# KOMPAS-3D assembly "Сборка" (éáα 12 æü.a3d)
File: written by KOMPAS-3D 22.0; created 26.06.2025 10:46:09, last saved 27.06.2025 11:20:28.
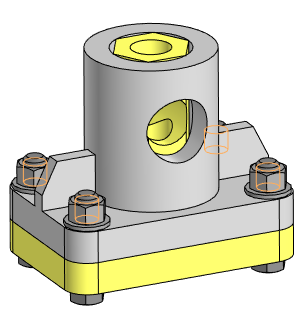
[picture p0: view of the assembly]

Document properties: Автор: Helen; Полное имя файла: C:\Для ноута\Инженерная графика\ППЭ 2025-2026\Варианты 1-38\Вариант 12 СБ\Вар 12 СБ\Вар 12 СБ.a3d

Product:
- Component [detail]: Сборка  | qty 4  | Масса: 0.008612; source file: ..\..\Вариант 8 СБ\Вар 8 СБ\Шайба 14.m3d
- Component [detail]: Сборка  | qty 4  | Масса: 0.02533; source file: ..\..\Вариант 8 СБ\Вар 8 СБ\Гайка М14.m3d
- Component [detail]: Болт М14x60 ГОСТ 15591-70  | qty 4  | Масса: 0.091885; source file: ..\..\Вариант 8 СБ\Вар 8 СБ\Болт М14x60 ГОСТ 15591-70.m3d
- Component [detail]: Основание  | designation Вариант 12  | qty 1  | Масса: 2.98152; source file: Основание вар 12.m3d
- Component [detail]: Nodes  | qty 1  | Масса: 3.992067; source file: Корпус вар 12.m3d
- Part/product: Сборка
    Масса: 7.476893

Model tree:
1. Массив по сетке:1  (with: Элемент выдавливания:5, Операция без истории:1, Элемент выдавливания:1)  (4 pattern instances)
     Шаг 1 = 120; Угол раствора = 90; Шаг 2 = 70

Referenced files in C:\Для ноута\Инженерная графика\ППЭ 2025-2026\Варианты 1-38\Вариант 12 СБ\Вар 12 СБ\: Основание вар 12.m3d, Корпус вар 12.m3d
Referenced files in C:\Для ноута\Инженерная графика\ППЭ 2025-2026\Варианты 1-38\Вариант 8 СБ\Вар 8 СБ\: Шайба 14.m3d, Гайка М14.m3d, Болт М14x60 ГОСТ 15591-70.m3d
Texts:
  Загружение0
  Сборка (1)
  Болт М14x60 ГОСТ 15591-70 (1)
  Вариант 12 Основание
